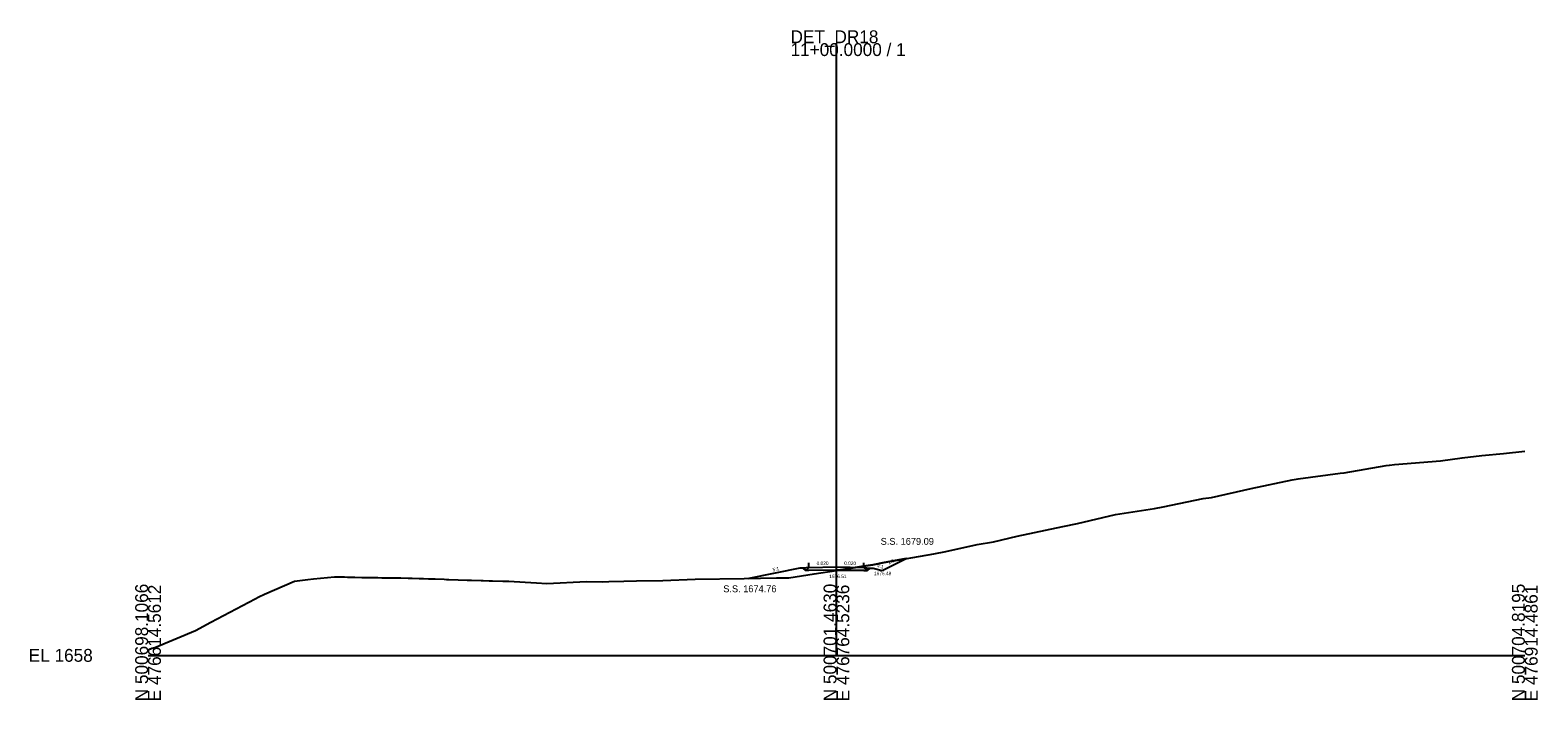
# Model space of a CAD drawing. Extents: x -26 to 303, y -10 to 3627.
# Drawn here: x -25.7 to 302.8, y 1990.3 to 2136.2 of the extents above; entities that cross this region are included whole.
import ezdxf

# ---------------------------------------------------------------- set-up
doc = ezdxf.new("R2010")
doc.units = 0
for name, color, linetype in [('Exist Cross Section Cell', 7, 'Continuous'), ('Exist XS Center Line Elevation Label', 7, 'Continuous'), ('Exist XS Ground Line', 7, 'Continuous'), ('Prop XS Ditch Slope Text', 7, 'Continuous'), ('Prop XS Ditch Standard Text', 7, 'Continuous'), ('Prop XS Dump Level', 7, 'Continuous'), ('Prop XS Earthwork Shape', 7, 'Continuous'), ('Prop XS EOT Tick Mark', 7, 'Continuous'), ('Prop XS Finish Grade', 7, 'Continuous'), ('Prop XS Finish Grade Earthwork', 7, 'Continuous'), ('Prop XS Finish Grade Pavement', 7, 'Continuous'), ('Prop XS Hydro Fill Slope Data', 7, 'Continuous'), ('Prop XS Hydro Typical Ditch Data', 7, 'Continuous'), ('Prop XS Pvmt Edge Slope', 7, 'Continuous'), ('Prop XS SE Text', 7, 'Continuous'), ('Prop XS Shoulder Borrow Shape', 7, 'Continuous'), ('Prop XS Side Slope Text', 7, 'Continuous'), ('Prop XS SS Elevation Text', 7, 'Continuous'), ('Prop XS Subgrade Earthwork', 7, 'Continuous')]:
    doc.layers.add(name, color=color, linetype=linetype)

msp = doc.modelspace()

# ---------------------------------------------------------------- linework, layer by layer
at = {"layer": 'Exist Cross Section Cell'}
for p, q in [((150, 2000), (150, 2133.4)), ((0, 2000), (150, 2000)), ((150, 2000), (300, 2000))]:
    msp.add_line(p, q, dxfattribs=at)
at = {"layer": 'Exist XS Ground Line'}
msp.add_lwpolyline([(0, 2001.17), (0.83, 2001.56), (1.45, 2001.75), (10.37, 2005.44), (13.7, 2007.21), (23.31, 2012.33), (24.14, 2012.72), (25.39, 2013.3), (31.92, 2016.2), (34.8, 2016.54), (36.06, 2016.67), (40.6, 2017.14), (41.06, 2017.13), (42.79, 2017.09), (43.47, 2017.07), (45.07, 2017.03), (46.56, 2017), (47.56, 2016.98), (49.18, 2016.96), (50.07, 2016.94), (50.96, 2016.93), (52.56, 2016.9), (54.15, 2016.87), (55.06, 2016.86), (56.7, 2016.82), (57.56, 2016.81), (59.07, 2016.78), (59.44, 2016.77), (60.01, 2016.75), (61.08, 2016.71), (62.54, 2016.65), (64.52, 2016.57), (65.03, 2016.55), (65.54, 2016.54), (67.54, 2016.48), (69.53, 2016.41), (70.04, 2016.39), (70.48, 2016.38), (72.55, 2016.31), (72.99, 2016.3), (74.32, 2016.27), (75.09, 2016.25), (77.32, 2016.18), (77.98, 2016.18), (78.6, 2016.14), (82.16, 2015.93), (84.61, 2015.78), (86.88, 2015.66), (95.53, 2016.08), (99.03, 2016.05), (100.42, 2016.07), (103.7, 2016.16), (106.46, 2016.22), (112.15, 2016.32), (119.21, 2016.64), (129.91, 2016.75), (133.48, 2016.8), (136.94, 2016.88), (139.6, 2016.87), (145.12, 2017.75), (150, 2018.51), (156.42, 2019.52), (157.95, 2019.75), (160.43, 2020.24), (171.25, 2022.15), (173.84, 2022.62), (180.65, 2024.18), (184.21, 2024.77), (189.37, 2025.94), (199.3, 2028.08), (202.56, 2028.73), (210.81, 2030.68), (219.32, 2031.98), (221.21, 2032.4), (229.9, 2034.16), (231.7, 2034.41), (240.37, 2036.37), (249.33, 2038.26), (250.61, 2038.5), (259.73, 2039.67), (260.62, 2039.79), (269.8, 2041.37), (270.54, 2041.47), (271.58, 2041.6), (281.66, 2042.4), (286.32, 2043.02), (290.66, 2043.52), (295.36, 2043.98), (300, 2044.47)], dxfattribs=at)
at = {"layer": 'Prop XS Dump Level'}
for p, q in [((144, 2019.14), (150, 2019.26)), ((150, 2019.26), (156, 2019.14))]:
    msp.add_line(p, q, dxfattribs=at)
at = {"layer": 'Prop XS Earthwork Shape'}
for points in [[(160, 2018.48), (165.22, 2021.09), (160.43, 2020.24), (157.95, 2019.75), (156.42, 2019.52), (150.43, 2018.58), (156, 2018.47), (156.68, 2018.46), (157.26, 2019.03), (158, 2018.98)], [(150, 2018.51), (150.43, 2018.58), (150, 2018.59), (144, 2018.47), (143.32, 2018.46), (142.74, 2019.03), (142, 2018.98), (130.93, 2016.76), (133.48, 2016.8), (136.94, 2016.88), (139.6, 2016.87), (145.12, 2017.75)]]:
    msp.add_lwpolyline(points, close=True, dxfattribs=at)
at = {"layer": 'Prop XS EOT Tick Mark'}
for p, q in [((144, 2019.14), (144, 2020.14)), ((156, 2019.14), (156, 2020.14))]:
    msp.add_line(p, q, dxfattribs=at)
at = {"layer": 'Prop XS Finish Grade'}
for p, q in [((144, 2019.14), (142.74, 2019.03)), ((156, 2019.14), (157.26, 2019.03))]:
    msp.add_line(p, q, dxfattribs=at)
at = {"layer": 'Prop XS Finish Grade Earthwork'}
for p, q in [((160, 2018.48), (165.22, 2021.09)), ((142, 2018.98), (130.93, 2016.76)), ((142.74, 2019.03), (142, 2018.98)), ((157.26, 2019.03), (158, 2018.98)), ((158, 2018.98), (160, 2018.48))]:
    msp.add_line(p, q, dxfattribs=at)
at = {"layer": 'Prop XS Finish Grade Pavement'}
for p, q in [((144, 2019.14), (150, 2019.26)), ((150, 2019.26), (156, 2019.14))]:
    msp.add_line(p, q, dxfattribs=at)
at = {"layer": 'Prop XS Hydro Fill Slope Data'}
msp.add_line((142, 2018.98), (130.93, 2016.76), dxfattribs=at)
at = {"layer": 'Prop XS Hydro Typical Ditch Data'}
for p, q in [((160, 2018.48), (165.22, 2021.09)), ((158, 2018.98), (160, 2018.48))]:
    msp.add_line(p, q, dxfattribs=at)
at = {"layer": 'Prop XS Pvmt Edge Slope'}
for p, q in [((144, 2019.14), (143.32, 2018.46)), ((156, 2019.14), (156.68, 2018.46))]:
    msp.add_line(p, q, dxfattribs=at)
at = {"layer": 'Prop XS Shoulder Borrow Shape'}
for points in [[(144, 2019.14), (142.74, 2019.03), (143.32, 2018.46)], [(144, 2019.14), (142.74, 2019.03), (143.32, 2018.46)], [(156, 2019.14), (157.26, 2019.03), (156.68, 2018.46)], [(156, 2019.14), (157.26, 2019.03), (156.68, 2018.46)]]:
    msp.add_lwpolyline(points, close=True, dxfattribs=at)
at = {"layer": 'Prop XS Subgrade Earthwork'}
for p, q in [((143.32, 2018.46), (142.74, 2019.03)), ((144, 2018.47), (143.32, 2018.46)), ((150, 2018.59), (144, 2018.47)), ((156, 2018.47), (150, 2018.59)), ((156, 2018.47), (156.68, 2018.46)), ((156.68, 2018.46), (157.26, 2019.03))]:
    msp.add_line(p, q, dxfattribs=at)

# ---------------------------------------------------------------- texts
at = {"layer": 'Exist Cross Section Cell'}
for s, p in [('DET_DR18', (140, 2133.4)), ('11+00.0000 / 1', (140, 2130.6)), ('EL 1658', (-26, 1998.6))]:
    msp.add_text(s, height=2.8, dxfattribs=at).set_placement(p)
for s, p in [('N 500698.1066', (0, 1990)), ('E 476614.5612', (2.8, 1990)), ('N 500701.4630', (150, 1990)), ('E 476764.5236', (152.8, 1990)), ('N 500704.8195', (300, 1990)), ('E 476914.4861', (302.8, 1990))]:
    msp.add_text(s, height=2.8, rotation=90, dxfattribs=at).set_placement(p)
at = {"layer": 'Exist XS Center Line Elevation Label'}
msp.add_text('1676.51', height=0.75, dxfattribs=at).set_placement((148.44, 2016.84))
at = {"layer": 'Prop XS Ditch Slope Text'}
msp.add_text('4:1', height=0.75, rotation=345.9638, dxfattribs=at).set_placement((158.79, 2019.25))
at = {"layer": 'Prop XS Ditch Standard Text'}
msp.add_text('1676.48', height=0.75, dxfattribs=at).set_placement((158.19, 2017.47))
at = {"layer": 'Prop XS Dump Level'}
for p in [(142, 2018.94), (158, 2018.94)]:
    msp.add_text('Case1', height=0.04, dxfattribs=at).set_placement(p)
at = {"layer": 'Prop XS SE Text'}
for rotation, p in [(1.1458, (145.69, 2019.67)), (358.8542, (151.69, 2019.72))]:
    msp.add_text('0.020', height=0.75, rotation=rotation, dxfattribs=at).set_placement(p)
at = {"layer": 'Prop XS Side Slope Text'}
for s, rotation, p in [('2:1', 26.5651, (161.41, 2019.79)), ('5:1', 11.3099, (136.17, 2018.27))]:
    msp.add_text(s, height=0.75, rotation=rotation, dxfattribs=at).set_placement(p)
at = {"layer": 'Prop XS SS Elevation Text'}
for s, p in [('S.S. 1679.09', (159.64, 2024.09)), ('S.S. 1674.76', (125.34, 2013.76))]:
    msp.add_text(s, height=1.5, dxfattribs=at).set_placement(p)

doc.saveas('drawing.dxf')
